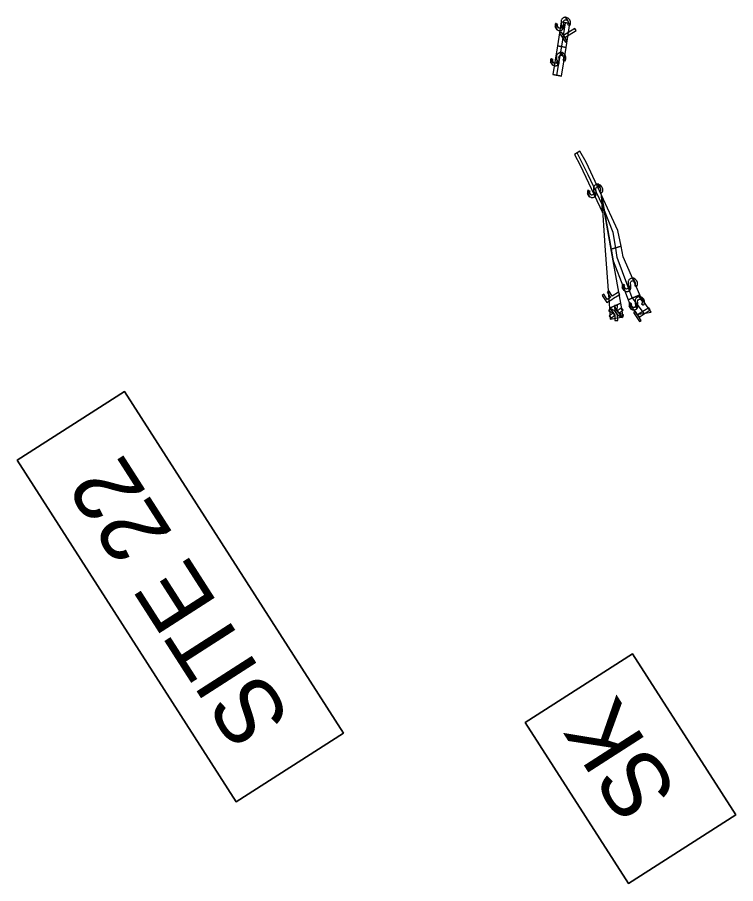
# Model space of a CAD drawing. Extents: x 474218 to 481634, y 484357 to 504997.
# Drawn here: x 477421.6 to 477585.8, y 499270.8 to 499468.6 of the extents above; entities that cross this region are included whole.
import ezdxf

# ---------------------------------------------------------------- set-up
doc = ezdxf.new("R2010")
doc.units = 0
for name, color, linetype in [('Exist Hydro Jurisdictional Stream or Body of Water', 7, 'Continuous'), ('Old_Level_29', 7, 'Continuous'), ('Prop Boundary Clearing Mechanized Hatching CELL', 7, 'Continuous'), ('Prop Earthen Structure Fill In Wetlands Hatching CELL', 7, 'Continuous'), ('Prop Earthen Structure Impacts In Surface Waters Hatching CELL', 7, 'Continuous'), ('Prop Grid Mask', 7, 'Continuous'), ('Scratch_Level_4', 7, 'Continuous'), ('Temp Earthen Structure Impacts In Surface Waters Hatching CELL', 7, 'Continuous')]:
    doc.layers.add(name, color=color, linetype=linetype)

msp = doc.modelspace()

# ---------------------------------------------------------------- linework, layer by layer
at = {"layer": 'Exist Hydro Jurisdictional Stream or Body of Water'}
msp.add_lwpolyline([(477561.29, 499270.76), (477537.68, 499307.56), (477562.16, 499323.27), (477585.77, 499286.46)], close=True, dxfattribs=at)
at = {"layer": 'Old_Level_29'}
msp.add_lwpolyline([(477471.65, 499289.43), (477421.62, 499367.42), (477446.11, 499383.12), (477496.14, 499305.14)], close=True, dxfattribs=at)
at = {"layer": 'Prop Boundary Clearing Mechanized Hatching CELL'}
msp.add_line((477559.5, 499403.3), (477556.92, 499402.19), dxfattribs=at)
msp.add_lwpolyline([(477556.92, 499402.19), (477557.1, 499399.67), (477560.06, 499400.17), (477559.5, 499403.3)], dxfattribs=at)
for points in [[(477557.83, 499401.02), (477557.85, 499401.01), (477557.18, 499402.06), (477557.15, 499402.07), (477557.05, 499402.13), (477556.74, 499401.51), (477557.73, 499401.07)], [(477558.79, 499400.54), (477558.78, 499400.6), (477558.15, 499401.58), (477558.16, 499401.52), (477557.18, 499402.06), (477557.85, 499401.01), (477557.84, 499401), (477558.15, 499400.52), (477558.15, 499400.42), (477558.16, 499399.32), (477558.16, 499399.32), (477558.84, 499399.35), (477558.83, 499399.46), (477558.83, 499399.49)], [(477558.72, 499401.73), (477558.73, 499402.78), (477558.06, 499402.76), (477558.07, 499402.57), (477558.71, 499401.57)], [(477559.68, 499400.08), (477559.83, 499399.99), (477559.17, 499401.03), (477559.04, 499401.08), (477558.72, 499401.57), (477558.71, 499401.57), (477558.07, 499402.57), (477558.15, 499401.58), (477558.78, 499400.6), (477559.66, 499400.09)], [(477559.61, 499401.42), (477560.05, 499401.67), (477559.68, 499402.26), (477559.27, 499401.96), (477559.26, 499401.96), (477558.79, 499401.62), (477558.72, 499401.57), (477559.04, 499401.08), (477559.11, 499401.12), (477559.61, 499401.42)], [(477558.1, 499400.49), (477558.15, 499400.52), (477557.84, 499401), (477557.79, 499400.98), (477556.84, 499400.44), (477557.21, 499399.86)], [(477560.14, 499400.59), (477560.14, 499400.6), (477560.13, 499400.6), (477559.17, 499401.03), (477559.83, 499399.99)]]:
    msp.add_lwpolyline(points, close=True, dxfattribs=at)
at = {"layer": 'Prop Earthen Structure Fill In Wetlands Hatching CELL'}
for p, q in [((477555.09, 499427.92), (477555.23, 499425.88)), ((477555.67, 499424.69), (477555.09, 499427.92)), ((477555.23, 499425.88), (477555.24, 499425.85)), ((477555.24, 499425.85), (477555.67, 499424.69)), ((477555.98, 499415.31), (477555.98, 499415.31)), ((477555.98, 499415.31), (477556.92, 499402.19)), ((477556.92, 499402.19), (477559.5, 499403.3)), ((477556.92, 499402.19), (477556.92, 499402.19))]:
    msp.add_line(p, q, dxfattribs=at)
for points in [[(477557.76, 499412.98), (477555.09, 499427.92), (477555.98, 499415.31)], [(477559.5, 499403.3), (477559.5, 499403.3), (477557.76, 499412.98)]]:
    msp.add_lwpolyline(points, dxfattribs=at)
msp.add_lwpolyline([(477557.88, 499404.42), (477559.27, 499405.31), (477558.97, 499405.79), (477557.58, 499404.89), (477556.83, 499406.07), (477556.41, 499405.8), (477557.16, 499404.62), (477556.42, 499404.15), (477555.67, 499405.33), (477555.26, 499405.06), (477556.32, 499403.41), (477556.73, 499403.68), (477557.46, 499404.15)], close=True, dxfattribs=at)
at = {"layer": 'Prop Earthen Structure Impacts In Surface Waters Hatching CELL'}
for p, q in [((477545.04, 499462.06), (477543.99, 499455.47)), ((477547, 499461.64), (477545.04, 499462.06)), ((477545.97, 499455.16), (477547, 499461.64)), ((477543.99, 499455.47), (477545.97, 499455.16)), ((477561.2, 499404.04), (477563.69, 499405.11))]:
    msp.add_line(p, q, dxfattribs=at)
for points in [[(477545.12, 499457.69), (477545.22, 499457.77), (477544.86, 499458.33), (477544.8, 499458.2), (477544.64, 499458.08), (477544.63, 499458.07), (477544.58, 499458.06), (477544.45, 499458.04), (477544.38, 499458.05), (477544.3, 499458.08), (477544.26, 499458.09), (477544.24, 499458.11), (477544.17, 499458.17), (477544.08, 499458.25), (477543.56, 499459.07), (477543.52, 499459.02), (477543.46, 499458.79), (477543.44, 499458.74), (477543.48, 499458.4), (477543.95, 499457.67), (477544.22, 499457.53), (477544.29, 499457.5), (477544.51, 499457.48), (477544.58, 499457.48), (477544.62, 499457.47), (477544.65, 499457.47), (477544.65, 499457.47), (477544.68, 499457.48), (477544.74, 499457.5), (477544.78, 499457.52), (477544.91, 499457.56), (477544.95, 499457.57), (477544.96, 499457.58)], [(477543.99, 499458.75), (477544.04, 499458.91), (477543.8, 499459.04), (477543.72, 499459.09), (477543.61, 499459.16), (477543.59, 499459.13), (477543.59, 499459.12), (477543.57, 499459.1), (477543.56, 499459.07), (477544.08, 499458.25), (477543.97, 499458.48), (477543.97, 499458.52), (477543.97, 499458.53), (477543.97, 499458.59), (477543.97, 499458.7)], [(477546.18, 499459.84), (477546.33, 499459.68), (477545.8, 499460.51), (477545.76, 499460.51), (477545.75, 499460.51), (477545.74, 499460.51), (477545.66, 499460.51), (477545.63, 499460.5), (477545.61, 499460.49), (477545.51, 499460.45), (477545.47, 499460.44), (477545.44, 499460.42), (477545.31, 499460.37), (477545.25, 499460.32), (477545.09, 499460.2), (477545.02, 499460.14), (477544.99, 499460.07), (477544.91, 499459.94), (477544.91, 499459.94), (477544.86, 499459.83), (477544.85, 499459.72), (477544.82, 499459.44), (477544.83, 499459.36), (477544.86, 499459.01), (477544.89, 499458.83), (477545.39, 499458.04), (477545.42, 499458.14), (477545.46, 499458.37), (477545.46, 499458.44), (477545.45, 499458.78), (477545.43, 499458.93), (477545.4, 499459.17), (477545.38, 499459.46), (477545.4, 499459.56), (477545.43, 499459.68), (477545.56, 499459.84), (477545.63, 499459.87), (477545.75, 499459.93), (477545.79, 499459.94), (477545.84, 499459.94), (477545.96, 499459.95), (477545.99, 499459.94), (477546.04, 499459.91), (477546.16, 499459.86), (477546.17, 499459.86)], [(477545.35, 499457.97), (477545.39, 499458.04), (477544.89, 499458.83), (477544.91, 499458.65), (477544.9, 499458.39), (477544.86, 499458.33), (477545.22, 499457.77), (477545.26, 499457.83)], [(477546.98, 499459.49), (477546.79, 499459.94), (477546.45, 499460.32), (477546.45, 499460.32), (477546.09, 499460.49), (477546.04, 499460.51), (477545.8, 499460.51), (477546.33, 499459.68), (477546.44, 499459.44), (477546.44, 499459.43), (477546.45, 499459.41), (477546.46, 499459.26), (477546.47, 499459.2), (477546.46, 499459.17), (477546.42, 499459.05), (477546.4, 499458.99), (477546.38, 499458.96), (477546.29, 499458.85), (477546.56, 499458.68), (477546.63, 499458.64), (477546.72, 499458.58), (477546.78, 499458.66), (477546.8, 499458.68), (477546.82, 499458.7), (477546.86, 499458.76), (477546.87, 499458.77), (477546.87, 499458.77), (477546.89, 499458.82), (477546.98, 499459.05), (477546.99, 499459.08), (477546.99, 499459.49)], [(477543.92, 499457.7), (477543.95, 499457.67), (477543.48, 499458.4), (477543.48, 499458.39), (477543.66, 499457.99), (477543.66, 499457.99)], [(477553.56, 499427.63), (477553.66, 499427.71), (477553.3, 499428.27), (477553.23, 499428.13), (477553.08, 499428.01), (477553.07, 499428.01), (477553.02, 499428), (477552.88, 499427.97), (477552.82, 499427.99), (477552.73, 499428.02), (477552.69, 499428.03), (477552.67, 499428.05), (477552.61, 499428.11), (477552.52, 499428.19), (477551.99, 499429.01), (477551.96, 499428.95), (477551.9, 499428.73), (477551.88, 499428.67), (477551.91, 499428.34), (477552.39, 499427.6), (477552.65, 499427.47), (477552.72, 499427.43), (477552.94, 499427.42), (477553.02, 499427.41), (477553.05, 499427.41), (477553.08, 499427.41), (477553.09, 499427.41), (477553.12, 499427.42), (477553.17, 499427.44), (477553.22, 499427.45), (477553.34, 499427.49), (477553.39, 499427.51), (477553.4, 499427.51)], [(477552.42, 499428.69), (477552.48, 499428.84), (477552.24, 499428.98), (477552.16, 499429.03), (477552.04, 499429.09), (477552.03, 499429.06), (477552.02, 499429.06), (477552.01, 499429.04), (477551.99, 499429.01), (477552.52, 499428.19), (477552.41, 499428.41), (477552.41, 499428.46), (477552.41, 499428.47), (477552.41, 499428.52), (477552.41, 499428.63)], [(477554.62, 499429.78), (477554.77, 499429.61), (477554.24, 499430.44), (477554.19, 499430.44), (477554.19, 499430.44), (477554.18, 499430.44), (477554.1, 499430.44), (477554.07, 499430.43), (477554.05, 499430.42), (477553.95, 499430.39), (477553.91, 499430.37), (477553.87, 499430.36), (477553.75, 499430.31), (477553.68, 499430.26), (477553.53, 499430.13), (477553.46, 499430.08), (477553.42, 499430.01), (477553.35, 499429.87), (477553.35, 499429.87), (477553.29, 499429.76), (477553.28, 499429.65), (477553.26, 499429.38), (477553.26, 499429.3), (477553.3, 499428.94), (477553.32, 499428.77), (477553.83, 499427.97), (477553.85, 499428.08), (477553.9, 499428.3), (477553.9, 499428.37), (477553.89, 499428.71), (477553.87, 499428.87), (477553.84, 499429.11), (477553.81, 499429.4), (477553.84, 499429.49), (477553.86, 499429.61), (477553.99, 499429.77), (477554.07, 499429.81), (477554.19, 499429.87), (477554.23, 499429.87), (477554.28, 499429.88), (477554.39, 499429.89), (477554.43, 499429.87), (477554.48, 499429.85), (477554.59, 499429.8), (477554.61, 499429.79)], [(477555.42, 499429.43), (477555.22, 499429.88), (477554.89, 499430.25), (477554.89, 499430.25), (477554.52, 499430.42), (477554.48, 499430.44), (477554.24, 499430.44), (477554.77, 499429.61), (477554.88, 499429.37), (477554.88, 499429.37), (477554.88, 499429.35), (477554.9, 499429.2), (477554.9, 499429.14), (477554.89, 499429.11), (477554.85, 499428.98), (477554.83, 499428.93), (477554.81, 499428.9), (477554.73, 499428.78), (477554.99, 499428.62), (477555.06, 499428.57), (477555.15, 499428.51), (477555.22, 499428.6), (477555.24, 499428.62), (477555.25, 499428.64), (477555.3, 499428.7), (477555.3, 499428.71), (477555.31, 499428.71), (477555.32, 499428.75), (477555.41, 499428.98), (477555.43, 499429.01), (477555.42, 499429.42)], [(477552.36, 499427.64), (477552.39, 499427.6), (477551.91, 499428.34), (477551.92, 499428.32), (477552.1, 499427.93), (477552.1, 499427.93)], [(477553.79, 499427.9), (477553.83, 499427.97), (477553.32, 499428.77), (477553.35, 499428.58), (477553.33, 499428.33), (477553.3, 499428.27), (477553.66, 499427.71), (477553.7, 499427.76)], [(477561.49, 499406.18), (477561.59, 499406.26), (477561.23, 499406.82), (477561.16, 499406.68), (477561.01, 499406.57), (477561, 499406.56), (477560.95, 499406.55), (477560.81, 499406.52), (477560.75, 499406.54), (477560.66, 499406.57), (477560.62, 499406.58), (477560.6, 499406.6), (477560.54, 499406.66), (477560.45, 499406.74), (477559.92, 499407.56), (477559.89, 499407.51), (477559.83, 499407.28), (477559.81, 499407.22), (477559.85, 499406.89), (477560.32, 499406.16), (477560.58, 499406.02), (477560.66, 499405.98), (477560.87, 499405.97), (477560.95, 499405.96), (477560.99, 499405.96), (477561.01, 499405.96), (477561.02, 499405.96), (477561.05, 499405.97), (477561.11, 499405.99), (477561.15, 499406), (477561.27, 499406.04), (477561.32, 499406.06), (477561.33, 499406.06)], [(477560.36, 499407.24), (477560.41, 499407.39), (477560.17, 499407.53), (477560.09, 499407.58), (477559.97, 499407.64), (477559.96, 499407.62), (477559.95, 499407.61), (477559.94, 499407.59), (477559.92, 499407.56), (477560.45, 499406.74), (477560.34, 499406.96), (477560.34, 499407.01), (477560.34, 499407.02), (477560.34, 499407.07), (477560.34, 499407.18)], [(477562.55, 499408.33), (477562.7, 499408.16), (477562.17, 499408.99), (477562.13, 499408.99), (477562.12, 499408.99), (477562.11, 499408.99), (477562.03, 499408.99), (477562, 499408.98), (477561.98, 499408.98), (477561.88, 499408.94), (477561.84, 499408.92), (477561.81, 499408.91), (477561.68, 499408.86), (477561.61, 499408.81), (477561.46, 499408.68), (477561.39, 499408.63), (477561.35, 499408.56), (477561.28, 499408.42), (477561.28, 499408.42), (477561.22, 499408.32), (477561.21, 499408.2), (477561.19, 499407.93), (477561.19, 499407.85), (477561.23, 499407.5), (477561.25, 499407.32), (477561.76, 499406.53), (477561.78, 499406.63), (477561.83, 499406.85), (477561.83, 499406.93), (477561.82, 499407.26), (477561.8, 499407.42), (477561.77, 499407.66), (477561.74, 499407.95), (477561.77, 499408.04), (477561.79, 499408.16), (477561.93, 499408.32), (477562, 499408.36), (477562.12, 499408.42), (477562.16, 499408.42), (477562.21, 499408.43), (477562.33, 499408.44), (477562.36, 499408.42), (477562.41, 499408.4), (477562.53, 499408.35), (477562.54, 499408.34)], [(477561.72, 499406.45), (477561.76, 499406.53), (477561.25, 499407.32), (477561.28, 499407.13), (477561.26, 499406.88), (477561.23, 499406.82), (477561.59, 499406.26), (477561.63, 499406.31)], [(477563.35, 499407.98), (477563.15, 499408.43), (477562.82, 499408.8), (477562.82, 499408.81), (477562.45, 499408.97), (477562.41, 499408.99), (477562.17, 499408.99), (477562.7, 499408.16), (477562.81, 499407.92), (477562.81, 499407.92), (477562.81, 499407.9), (477562.83, 499407.75), (477562.83, 499407.69), (477562.82, 499407.66), (477562.78, 499407.53), (477562.77, 499407.48), (477562.74, 499407.45), (477562.66, 499407.33), (477562.92, 499407.17), (477562.99, 499407.12), (477563.08, 499407.07), (477563.15, 499407.15), (477563.17, 499407.17), (477563.18, 499407.19), (477563.23, 499407.25), (477563.24, 499407.26), (477563.24, 499407.26), (477563.25, 499407.3), (477563.35, 499407.53), (477563.36, 499407.56), (477563.35, 499407.97)], [(477560.29, 499406.19), (477560.32, 499406.16), (477559.85, 499406.89), (477559.85, 499406.88), (477560.03, 499406.48), (477560.03, 499406.48)]]:
    msp.add_lwpolyline(points, close=True, dxfattribs=at)
for points in [[(477555.09, 499427.92), (477555.09, 499427.92), (477552.66, 499433.19), (477551.59, 499435.5), (477550.17, 499438.02), (477548.94, 499437.22), (477550.2, 499434.82), (477555.37, 499423.97), (477555.09, 499427.92), (477555.09, 499427.92), (477557.28, 499415.66), (477557.28, 499415.66), (477557.28, 499415.66), (477557.28, 499415.66), (477557.28, 499415.66)], [(477557.28, 499415.66), (477557.28, 499415.66), (477559.58, 499416.28), (477558.87, 499419.92), (477555.09, 499427.92)], [(477563.69, 499405.11), (477563.83, 499405.17), (477560.05, 499413.88), (477559.58, 499416.28), (477557.28, 499415.66), (477557.28, 499415.66), (477557.28, 499415.66), (477557.28, 499415.66), (477557.76, 499412.98), (477560.13, 499406.84), (477561.2, 499404.04), (477561.2, 499404.04)]]:
    msp.add_lwpolyline(points, dxfattribs=at)
at = {"layer": 'Prop Grid Mask'}
for points in [[(477496.14, 499305.14), (477446.11, 499383.12), (477421.62, 499367.42), (477471.65, 499289.43)], [(477585.77, 499286.46), (477562.16, 499323.27), (477537.68, 499307.56), (477561.29, 499270.76)]]:
    msp.add_lwpolyline(points, close=True, dxfattribs=at)
at = {"layer": 'Scratch_Level_4'}
for p, q in [((477545.91, 499467.49), (477547.88, 499467.18)), ((477544.89, 499455.34), (477546.06, 499461.97)), ((477545.97, 499455.16), (477543.99, 499455.47)), ((477562.08, 499404.5), (477564.77, 499400.97))]:
    msp.add_line(p, q, dxfattribs=at)
for points in [[(477546.06, 499461.97), (477546.06, 499461.97), (477546.89, 499467.29)], [(477555.24, 499425.85), (477552.09, 499432.58), (477549.52, 499437.6)], [(477558.38, 499415.89), (477557.75, 499419.42), (477555.64, 499424.84)], [(477562.08, 499404.5), (477558.71, 499413.72), (477558.38, 499415.89)]]:
    msp.add_lwpolyline(points, dxfattribs=at)
at = {"layer": 'Temp Earthen Structure Impacts In Surface Waters Hatching CELL'}
for p, q in [((477545.91, 499467.49), (477545.04, 499462.06)), ((477547.88, 499467.18), (477545.91, 499467.49)), ((477547, 499461.64), (477547.88, 499467.18)), ((477545.04, 499462.06), (477547, 499461.64))]:
    msp.add_line(p, q, dxfattribs=at)
for points in [[(477547.24, 499467.89), (477547.39, 499467.73), (477546.86, 499468.56), (477546.81, 499468.56), (477546.81, 499468.56), (477546.8, 499468.56), (477546.71, 499468.56), (477546.69, 499468.55), (477546.67, 499468.54), (477546.57, 499468.5), (477546.53, 499468.49), (477546.49, 499468.47), (477546.37, 499468.42), (477546.3, 499468.37), (477546.14, 499468.25), (477546.08, 499468.19), (477546.04, 499468.12), (477545.97, 499467.99), (477545.97, 499467.99), (477545.91, 499467.88), (477545.9, 499467.77), (477545.87, 499467.49), (477545.88, 499467.41), (477545.91, 499467.06), (477545.94, 499466.88), (477546.45, 499466.09), (477546.47, 499466.19), (477546.52, 499466.41), (477546.52, 499466.49), (477546.51, 499466.82), (477546.49, 499466.98), (477546.46, 499467.22), (477546.43, 499467.51), (477546.45, 499467.61), (477546.48, 499467.72), (477546.61, 499467.89), (477546.69, 499467.92), (477546.81, 499467.98), (477546.85, 499467.99), (477546.9, 499467.99), (477547.01, 499468), (477547.05, 499467.98), (477547.1, 499467.96), (477547.21, 499467.91), (477547.23, 499467.9)], [(477548.04, 499467.54), (477547.84, 499467.99), (477547.51, 499468.37), (477547.51, 499468.37), (477547.14, 499468.53), (477547.1, 499468.55), (477546.86, 499468.56), (477547.39, 499467.73), (477547.5, 499467.49), (477547.5, 499467.48), (477547.5, 499467.46), (477547.52, 499467.31), (477547.52, 499467.25), (477547.51, 499467.22), (477547.47, 499467.1), (477547.45, 499467.04), (477547.43, 499467.01), (477547.35, 499466.9), (477547.61, 499466.73), (477547.68, 499466.68), (477547.77, 499466.63), (477547.84, 499466.71), (477547.85, 499466.73), (477547.87, 499466.75), (477547.92, 499466.81), (477547.92, 499466.82), (477547.92, 499466.82), (477547.94, 499466.87), (477548.03, 499467.09), (477548.05, 499467.12), (477548.04, 499467.54)], [(477546.18, 499465.74), (477546.28, 499465.82), (477545.92, 499466.38), (477545.85, 499466.25), (477545.7, 499466.13), (477545.68, 499466.12), (477545.64, 499466.11), (477545.5, 499466.08), (477545.44, 499466.1), (477545.35, 499466.13), (477545.31, 499466.14), (477545.29, 499466.16), (477545.22, 499466.22), (477545.14, 499466.3), (477544.61, 499467.12), (477544.58, 499467.07), (477544.51, 499466.84), (477544.5, 499466.79), (477544.53, 499466.45), (477545, 499465.72), (477545.27, 499465.58), (477545.34, 499465.55), (477545.56, 499465.53), (477545.64, 499465.53), (477545.67, 499465.52), (477545.7, 499465.52), (477545.71, 499465.52), (477545.73, 499465.53), (477545.79, 499465.55), (477545.84, 499465.56), (477545.96, 499465.61), (477546.01, 499465.62), (477546.02, 499465.62)], [(477545.04, 499466.8), (477545.1, 499466.95), (477544.86, 499467.09), (477544.77, 499467.14), (477544.66, 499467.2), (477544.65, 499467.18), (477544.64, 499467.17), (477544.63, 499467.15), (477544.61, 499467.12), (477545.14, 499466.3), (477545.03, 499466.53), (477545.03, 499466.57), (477545.03, 499466.58), (477545.03, 499466.63), (477545.03, 499466.75)], [(477546.4, 499466.02), (477546.45, 499466.09), (477545.94, 499466.88), (477545.97, 499466.7), (477545.95, 499466.44), (477545.92, 499466.38), (477546.28, 499465.82), (477546.31, 499465.87)], [(477544.97, 499465.75), (477545, 499465.72), (477544.53, 499466.45), (477544.53, 499466.44), (477544.72, 499466.04), (477544.72, 499466.04)], [(477546.85, 499462.87), (477547.26, 499463.13), (477545.95, 499465.18), (477545.54, 499464.91)], [(477546.76, 499463.92), (477549.3, 499465.55), (477548.99, 499466.03), (477546.45, 499464.39)], [(477563.09, 499401.95), (477563.2, 499402.03), (477562.84, 499402.59), (477562.77, 499402.46), (477562.61, 499402.34), (477562.6, 499402.33), (477562.55, 499402.32), (477562.42, 499402.3), (477562.36, 499402.32), (477562.27, 499402.34), (477562.23, 499402.36), (477562.21, 499402.37), (477562.14, 499402.44), (477562.06, 499402.52), (477561.53, 499403.34), (477561.49, 499403.28), (477561.43, 499403.05), (477561.42, 499403), (477561.45, 499402.67), (477561.92, 499401.93), (477562.19, 499401.8), (477562.26, 499401.76), (477562.48, 499401.74), (477562.55, 499401.74), (477562.59, 499401.74), (477562.62, 499401.73), (477562.63, 499401.74), (477562.65, 499401.75), (477562.71, 499401.76), (477562.75, 499401.78), (477562.88, 499401.82), (477562.93, 499401.83), (477562.94, 499401.84)], [(477561.96, 499403.01), (477562.01, 499403.17), (477561.77, 499403.31), (477561.69, 499403.35), (477561.58, 499403.42), (477561.56, 499403.39), (477561.56, 499403.39), (477561.55, 499403.36), (477561.53, 499403.34), (477562.06, 499402.52), (477561.95, 499402.74), (477561.95, 499402.78), (477561.95, 499402.8), (477561.95, 499402.85), (477561.94, 499402.96)], [(477564.16, 499404.11), (477564.31, 499403.94), (477563.78, 499404.77), (477563.73, 499404.77), (477563.73, 499404.77), (477563.72, 499404.77), (477563.63, 499404.77), (477563.61, 499404.76), (477563.59, 499404.75), (477563.49, 499404.71), (477563.45, 499404.7), (477563.41, 499404.69), (477563.28, 499404.64), (477563.22, 499404.59), (477563.06, 499404.46), (477563, 499404.41), (477562.96, 499404.34), (477562.89, 499404.2), (477562.89, 499404.2), (477562.83, 499404.09), (477562.82, 499403.98), (477562.79, 499403.7), (477562.8, 499403.62), (477562.83, 499403.27), (477562.86, 499403.09), (477563.37, 499402.3), (477563.39, 499402.4), (477563.44, 499402.63), (477563.44, 499402.7), (477563.42, 499403.04), (477563.41, 499403.19), (477563.38, 499403.43), (477563.35, 499403.72), (477563.37, 499403.82), (477563.4, 499403.94), (477563.53, 499404.1), (477563.61, 499404.14), (477563.73, 499404.2), (477563.77, 499404.2), (477563.82, 499404.2), (477563.93, 499404.21), (477563.97, 499404.2), (477564.01, 499404.18), (477564.13, 499404.12), (477564.15, 499404.12)], [(477564.96, 499403.76), (477564.76, 499404.2), (477564.43, 499404.58), (477564.43, 499404.58), (477564.06, 499404.75), (477564.02, 499404.77), (477563.78, 499404.77), (477564.31, 499403.94), (477564.42, 499403.7), (477564.42, 499403.69), (477564.42, 499403.67), (477564.43, 499403.52), (477564.44, 499403.46), (477564.43, 499403.44), (477564.39, 499403.31), (477564.37, 499403.25), (477564.35, 499403.22), (477564.27, 499403.11), (477564.53, 499402.94), (477564.6, 499402.9), (477564.69, 499402.84), (477564.76, 499402.93), (477564.77, 499402.94), (477564.79, 499402.97), (477564.84, 499403.02), (477564.84, 499403.03), (477564.84, 499403.04), (477564.86, 499403.08), (477564.95, 499403.31), (477564.96, 499403.34), (477564.96, 499403.75)], [(477561.89, 499401.96), (477561.92, 499401.93), (477561.45, 499402.67), (477561.45, 499402.65), (477561.64, 499402.25), (477561.64, 499402.25)], [(477563.77, 499399.08), (477564.18, 499399.34), (477562.87, 499401.39), (477562.45, 499401.13)], [(477563.32, 499402.23), (477563.37, 499402.3), (477562.86, 499403.09), (477562.89, 499402.91), (477562.87, 499402.65), (477562.84, 499402.59), (477563.2, 499402.03), (477563.23, 499402.09)], [(477563.68, 499400.13), (477566.22, 499401.76), (477565.91, 499402.24), (477563.37, 499400.61)]]:
    msp.add_lwpolyline(points, close=True, dxfattribs=at)
msp.add_lwpolyline([(477563.17, 499400.69), (477566.43, 499401.24), (477564.02, 499404.73), (477563.83, 499405.17), (477561.2, 499404.04), (477561.65, 499402.88), (477563.17, 499400.69)], dxfattribs=at)

# ---------------------------------------------------------------- texts
at = {"layer": 'Exist Hydro Jurisdictional Stream or Body of Water'}
msp.add_text('SK', height=15, rotation=122.6822, dxfattribs=at).set_placement((477572.84, 499291.62))
at = {"layer": 'Old_Level_29'}
msp.add_text('SITE 22', height=15, rotation=122.6822, dxfattribs=at).set_placement((477484.45, 499308.38))

doc.saveas('drawing.dxf')
